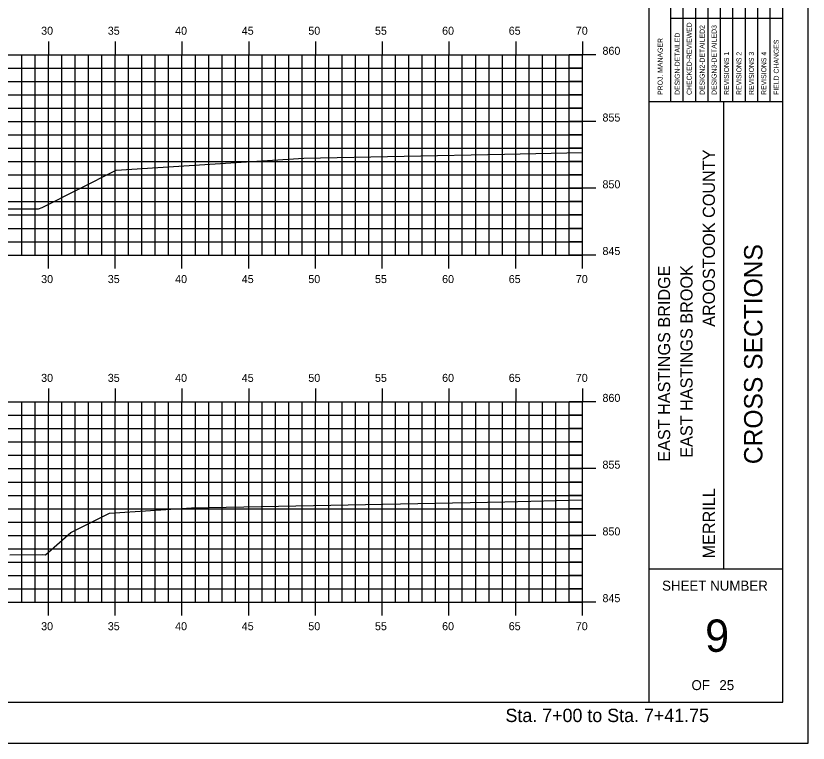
# Model space of a CAD drawing. Extents: x 2194004 to 2194525, y 863888 to 863998.
# Drawn here: x 2194282.5 to 2194341.9, y 863888.4 to 863942.9 of the extents above; entities that cross this region are included whole.
import ezdxf

# ---------------------------------------------------------------- set-up
doc = ezdxf.new("R2010")
doc.units = 0
for name, color, linetype in [('BORDER', 7, 'Continuous'), ('BRIDGE_TITLE', 7, 'Continuous'), ('H_V ANNOTATION', 7, 'Continuous'), ('MAJOR', 7, 'Continuous'), ('MINOR', 7, 'Continuous'), ('PLOT BOUNDARY', 7, 'Continuous'), ('S_Roadway_Centerline', 7, 'Continuous')]:
    doc.layers.add(name, color=color, linetype=linetype)

msp = doc.modelspace()

# ---------------------------------------------------------------- linework, layer by layer
at = {"layer": 'BORDER'}
for p, q in [((2194329.986, 863891.446), (2194329.986, 863996.446)), ((2194329.986, 863936.449), (2194339.986, 863936.449)), ((2194335.577, 863901.449), (2194335.577, 863936.449)), ((2194329.986, 863901.449), (2194339.986, 863901.449))]:
    msp.add_line(p, q, dxfattribs=at)
msp.add_lwpolyline([(2194179.986, 863891.446), (2194339.986, 863891.446), (2194339.986, 863996.446), (2194179.986, 863996.446)], close=True, dxfattribs=at)
for points in [[(2194332.534, 863936.452), (2194332.534, 863953.949)], [(2194333.466, 863953.949), (2194333.466, 863936.452)], [(2194334.397, 863936.452), (2194334.397, 863953.949)], [(2194335.329, 863936.452), (2194335.329, 863953.949)], [(2194336.261, 863936.452), (2194336.261, 863953.949)], [(2194337.192, 863936.452), (2194337.192, 863953.949)], [(2194338.124, 863936.452), (2194338.124, 863953.949)], [(2194339.056, 863936.452), (2194339.056, 863953.949)], [(2194331.602, 863936.452), (2194331.602, 863953.243)], [(2194331.601, 863942.699), (2194339.986, 863942.699)]]:
    msp.add_lwpolyline(points, dxfattribs=at)
at = {"layer": 'MAJOR'}
for p, q in [((2194284.986, 863940.948), (2194284.986, 863939.946)), ((2194289.986, 863940.948), (2194289.986, 863939.946)), ((2194294.986, 863940.948), (2194294.986, 863939.946)), ((2194299.986, 863940.948), (2194299.986, 863939.946)), ((2194304.986, 863940.948), (2194304.986, 863939.946)), ((2194309.986, 863940.948), (2194309.986, 863939.946)), ((2194314.986, 863940.948), (2194314.986, 863939.946)), ((2194319.986, 863940.948), (2194319.986, 863939.946)), ((2194324.986, 863940.948), (2194324.986, 863939.946)), ((2194184.986, 863939.946), (2194324.986, 863939.946)), ((2194184.986, 863939.946), (2194324.986, 863939.946)), ((2194284.986, 863924.946), (2194284.986, 863939.946)), ((2194289.986, 863924.946), (2194289.986, 863939.946)), ((2194294.986, 863924.946), (2194294.986, 863939.946)), ((2194299.986, 863924.946), (2194299.986, 863939.946)), ((2194304.986, 863924.946), (2194304.986, 863939.946)), ((2194309.986, 863924.946), (2194309.986, 863939.946)), ((2194314.986, 863924.946), (2194314.986, 863939.946)), ((2194319.986, 863924.946), (2194319.986, 863939.946)), ((2194325.988, 863939.946), (2194323.984, 863939.946)), ((2194324.986, 863924.946), (2194324.986, 863939.946)), ((2194324.986, 863924.946), (2194324.986, 863939.946)), ((2194184.986, 863934.946), (2194324.986, 863934.946)), ((2194325.988, 863934.946), (2194323.984, 863934.946)), ((2194184.986, 863929.946), (2194324.986, 863929.946)), ((2194325.988, 863929.946), (2194323.984, 863929.946)), ((2194184.986, 863924.946), (2194324.986, 863924.946)), ((2194284.986, 863923.944), (2194284.986, 863924.946)), ((2194289.986, 863923.944), (2194289.986, 863924.946)), ((2194294.986, 863923.944), (2194294.986, 863924.946)), ((2194299.986, 863923.944), (2194299.986, 863924.946)), ((2194304.986, 863923.944), (2194304.986, 863924.946)), ((2194309.986, 863923.944), (2194309.986, 863924.946)), ((2194314.986, 863923.944), (2194314.986, 863924.946)), ((2194319.986, 863923.944), (2194319.986, 863924.946)), ((2194325.988, 863924.946), (2194323.984, 863924.946)), ((2194324.986, 863923.944), (2194324.986, 863924.946)), ((2194284.986, 863914.948), (2194284.986, 863913.946)), ((2194289.986, 863914.948), (2194289.986, 863913.946)), ((2194294.986, 863914.948), (2194294.986, 863913.946)), ((2194299.986, 863914.948), (2194299.986, 863913.946)), ((2194304.986, 863914.948), (2194304.986, 863913.946)), ((2194309.986, 863914.948), (2194309.986, 863913.946)), ((2194314.986, 863914.948), (2194314.986, 863913.946)), ((2194319.986, 863914.948), (2194319.986, 863913.946)), ((2194324.986, 863914.948), (2194324.986, 863913.946)), ((2194184.986, 863913.946), (2194324.986, 863913.946)), ((2194184.986, 863913.946), (2194324.986, 863913.946)), ((2194284.986, 863898.946), (2194284.986, 863913.946)), ((2194289.986, 863898.946), (2194289.986, 863913.946)), ((2194294.986, 863898.946), (2194294.986, 863913.946)), ((2194299.986, 863898.946), (2194299.986, 863913.946)), ((2194304.986, 863898.946), (2194304.986, 863913.946)), ((2194309.986, 863898.946), (2194309.986, 863913.946)), ((2194314.986, 863898.946), (2194314.986, 863913.946)), ((2194319.986, 863898.946), (2194319.986, 863913.946)), ((2194325.988, 863913.946), (2194323.984, 863913.946)), ((2194324.986, 863898.946), (2194324.986, 863913.946)), ((2194324.986, 863898.946), (2194324.986, 863913.946)), ((2194184.986, 863908.946), (2194324.986, 863908.946)), ((2194325.988, 863908.946), (2194323.984, 863908.946)), ((2194184.986, 863903.946), (2194324.986, 863903.946)), ((2194325.988, 863903.946), (2194323.984, 863903.946)), ((2194184.986, 863898.946), (2194324.986, 863898.946)), ((2194284.986, 863897.944), (2194284.986, 863898.946)), ((2194289.986, 863897.944), (2194289.986, 863898.946)), ((2194294.986, 863897.944), (2194294.986, 863898.946)), ((2194299.986, 863897.944), (2194299.986, 863898.946)), ((2194304.986, 863897.944), (2194304.986, 863898.946)), ((2194309.986, 863897.944), (2194309.986, 863898.946)), ((2194314.986, 863897.944), (2194314.986, 863898.946)), ((2194319.986, 863897.944), (2194319.986, 863898.946)), ((2194325.988, 863898.946), (2194323.984, 863898.946)), ((2194324.986, 863897.944), (2194324.986, 863898.946))]:
    msp.add_line(p, q, dxfattribs=at)
at = {"layer": 'MINOR'}
for p, q in [((2194282.986, 863924.946), (2194282.986, 863939.946)), ((2194283.986, 863924.946), (2194283.986, 863939.946)), ((2194285.986, 863924.946), (2194285.986, 863939.946)), ((2194286.986, 863924.946), (2194286.986, 863939.946)), ((2194287.986, 863924.946), (2194287.986, 863939.946)), ((2194288.986, 863924.946), (2194288.986, 863939.946)), ((2194290.986, 863924.946), (2194290.986, 863939.946)), ((2194291.986, 863924.946), (2194291.986, 863939.946)), ((2194292.986, 863924.946), (2194292.986, 863939.946)), ((2194293.986, 863924.946), (2194293.986, 863939.946)), ((2194295.986, 863924.946), (2194295.986, 863939.946)), ((2194296.986, 863924.946), (2194296.986, 863939.946)), ((2194297.986, 863924.946), (2194297.986, 863939.946)), ((2194298.986, 863924.946), (2194298.986, 863939.946)), ((2194300.986, 863924.946), (2194300.986, 863939.946)), ((2194301.986, 863924.946), (2194301.986, 863939.946)), ((2194302.986, 863924.946), (2194302.986, 863939.946)), ((2194303.986, 863924.946), (2194303.986, 863939.946)), ((2194305.986, 863924.946), (2194305.986, 863939.946)), ((2194306.986, 863924.946), (2194306.986, 863939.946)), ((2194307.986, 863924.946), (2194307.986, 863939.946)), ((2194308.986, 863924.946), (2194308.986, 863939.946)), ((2194310.986, 863924.946), (2194310.986, 863939.946)), ((2194311.986, 863924.946), (2194311.986, 863939.946)), ((2194312.986, 863924.946), (2194312.986, 863939.946)), ((2194313.986, 863924.946), (2194313.986, 863939.946)), ((2194315.986, 863924.946), (2194315.986, 863939.946)), ((2194316.986, 863924.946), (2194316.986, 863939.946)), ((2194317.986, 863924.946), (2194317.986, 863939.946)), ((2194318.986, 863924.946), (2194318.986, 863939.946)), ((2194320.986, 863924.946), (2194320.986, 863939.946)), ((2194321.986, 863924.946), (2194321.986, 863939.946)), ((2194322.986, 863924.946), (2194322.986, 863939.946)), ((2194323.986, 863924.946), (2194323.986, 863939.946)), ((2194184.986, 863938.946), (2194324.986, 863938.946)), ((2194324.986, 863938.946), (2194323.984, 863938.946)), ((2194184.986, 863937.946), (2194324.986, 863937.946)), ((2194324.986, 863937.946), (2194323.984, 863937.946)), ((2194184.986, 863936.946), (2194324.986, 863936.946)), ((2194324.986, 863936.946), (2194323.984, 863936.946)), ((2194184.986, 863935.946), (2194324.986, 863935.946)), ((2194324.986, 863935.946), (2194323.984, 863935.946)), ((2194184.986, 863933.946), (2194324.986, 863933.946)), ((2194324.986, 863933.946), (2194323.984, 863933.946)), ((2194184.986, 863932.946), (2194324.986, 863932.946)), ((2194324.986, 863932.946), (2194323.984, 863932.946)), ((2194184.986, 863931.946), (2194324.986, 863931.946)), ((2194324.986, 863931.946), (2194323.984, 863931.946)), ((2194184.986, 863930.946), (2194324.986, 863930.946)), ((2194324.986, 863930.946), (2194323.984, 863930.946)), ((2194184.986, 863928.946), (2194324.986, 863928.946)), ((2194324.986, 863928.946), (2194323.984, 863928.946)), ((2194184.986, 863927.946), (2194324.986, 863927.946)), ((2194324.986, 863927.946), (2194323.984, 863927.946)), ((2194184.986, 863926.946), (2194324.986, 863926.946)), ((2194324.986, 863926.946), (2194323.984, 863926.946)), ((2194184.986, 863925.946), (2194324.986, 863925.946)), ((2194324.986, 863925.946), (2194323.984, 863925.946)), ((2194282.986, 863898.946), (2194282.986, 863913.946)), ((2194283.986, 863898.946), (2194283.986, 863913.946)), ((2194285.986, 863898.946), (2194285.986, 863913.946)), ((2194286.986, 863898.946), (2194286.986, 863913.946)), ((2194287.986, 863898.946), (2194287.986, 863913.946)), ((2194288.986, 863898.946), (2194288.986, 863913.946)), ((2194290.986, 863898.946), (2194290.986, 863913.946)), ((2194291.986, 863898.946), (2194291.986, 863913.946)), ((2194292.986, 863898.946), (2194292.986, 863913.946)), ((2194293.986, 863898.946), (2194293.986, 863913.946)), ((2194295.986, 863898.946), (2194295.986, 863913.946)), ((2194296.986, 863898.946), (2194296.986, 863913.946)), ((2194297.986, 863898.946), (2194297.986, 863913.946)), ((2194298.986, 863898.946), (2194298.986, 863913.946)), ((2194300.986, 863898.946), (2194300.986, 863913.946)), ((2194301.986, 863898.946), (2194301.986, 863913.946)), ((2194302.986, 863898.946), (2194302.986, 863913.946)), ((2194303.986, 863898.946), (2194303.986, 863913.946)), ((2194305.986, 863898.946), (2194305.986, 863913.946)), ((2194306.986, 863898.946), (2194306.986, 863913.946)), ((2194307.986, 863898.946), (2194307.986, 863913.946)), ((2194308.986, 863898.946), (2194308.986, 863913.946)), ((2194310.986, 863898.946), (2194310.986, 863913.946)), ((2194311.986, 863898.946), (2194311.986, 863913.946)), ((2194312.986, 863898.946), (2194312.986, 863913.946)), ((2194313.986, 863898.946), (2194313.986, 863913.946)), ((2194315.986, 863898.946), (2194315.986, 863913.946)), ((2194316.986, 863898.946), (2194316.986, 863913.946)), ((2194317.986, 863898.946), (2194317.986, 863913.946)), ((2194318.986, 863898.946), (2194318.986, 863913.946)), ((2194320.986, 863898.946), (2194320.986, 863913.946)), ((2194321.986, 863898.946), (2194321.986, 863913.946)), ((2194322.986, 863898.946), (2194322.986, 863913.946)), ((2194323.986, 863898.946), (2194323.986, 863913.946)), ((2194184.986, 863912.946), (2194324.986, 863912.946)), ((2194324.986, 863912.946), (2194323.984, 863912.946)), ((2194184.986, 863911.946), (2194324.986, 863911.946)), ((2194324.986, 863911.946), (2194323.984, 863911.946)), ((2194184.986, 863910.946), (2194324.986, 863910.946)), ((2194324.986, 863910.946), (2194323.984, 863910.946)), ((2194184.986, 863909.946), (2194324.986, 863909.946)), ((2194324.986, 863909.946), (2194323.984, 863909.946)), ((2194184.986, 863907.946), (2194324.986, 863907.946)), ((2194324.986, 863907.946), (2194323.984, 863907.946)), ((2194184.986, 863906.946), (2194324.986, 863906.946)), ((2194324.986, 863906.946), (2194323.984, 863906.946)), ((2194184.986, 863905.946), (2194324.986, 863905.946)), ((2194324.986, 863905.946), (2194323.984, 863905.946)), ((2194184.986, 863904.946), (2194324.986, 863904.946)), ((2194324.986, 863904.946), (2194323.984, 863904.946)), ((2194184.986, 863902.946), (2194324.986, 863902.946)), ((2194324.986, 863902.946), (2194323.984, 863902.946)), ((2194184.986, 863901.946), (2194324.986, 863901.946)), ((2194324.986, 863901.946), (2194323.984, 863901.946)), ((2194184.986, 863900.946), (2194324.986, 863900.946)), ((2194324.986, 863900.946), (2194323.984, 863900.946)), ((2194184.986, 863899.946), (2194324.986, 863899.946)), ((2194324.986, 863899.946), (2194323.984, 863899.946))]:
    msp.add_line(p, q, dxfattribs=at)
at = {"layer": 'PLOT BOUNDARY'}
msp.add_lwpolyline([(2194171.893, 863888.387), (2194341.893, 863888.387), (2194341.893, 863998.387), (2194171.893, 863998.387)], close=True, dxfattribs=at)
at = {"layer": 'S_Roadway_Centerline'}
for points in [[(2194281.523, 863928.402), (2194284.108, 863928.415), (2194284.225, 863928.403), (2194284.505, 863928.498), (2194290.063, 863931.291), (2194304.109, 863932.211), (2194319.136, 863932.499), (2194324.986, 863932.636)], [(2194282.094, 863902.5), (2194284.53, 863902.509), (2194284.77, 863902.497), (2194286.649, 863904.16), (2194289.544, 863905.615), (2194295.708, 863906.019), (2194319.166, 863906.469), (2194324.986, 863906.605)]]:
    msp.add_lwpolyline(points, dxfattribs=at)

# ---------------------------------------------------------------- texts
at = {"layer": 'BORDER'}
for s, height, rotation, p in [('CHECKED-REVIEWED', 0.37275, 90, (2194333.167, 863936.937)), ('DESIGN2-DETAILED2', 0.37275, 90, (2194334.136, 863936.937)), ('DESIGN3-DETAILED3', 0.37275, 90, (2194335.031, 863936.937)), ('PROJ. MANAGER', 0.37275, 90, (2194330.991, 863936.937)), ('DESIGN-DETAILED', 0.37275, 90, (2194332.273, 863936.937)), ('FIELD CHANGES', 0.37275, 90, (2194339.689, 863936.937)), ('REVISIONS 1', 0.37275, 90, (2194335.962, 863936.937)), ('REVISIONS 2', 0.37275, 90, (2194336.894, 863936.937)), ('REVISIONS 3', 0.37275, 90, (2194337.826, 863936.937)), ('REVISIONS 4', 0.37275, 90, (2194338.758, 863936.937)), ('CROSS SECTIONS', 1.37787, 90, (2194338.471, 863909.283)), ('SHEET NUMBER', 0.74527, 360, (2194330.952, 863899.812)), ('9', 2.419, 360, (2194334.173, 863895.228)), ('OF', 0.7453, 360, (2194333.153, 863892.359)), ('25', 0.7453, 360, (2194335.243, 863892.359))]:
    msp.add_text(s, height=height, rotation=rotation, dxfattribs=at).set_placement(p)
at = {"layer": 'BRIDGE_TITLE'}
for s, height, p in [('AROOSTOOK COUNTY', 0.90716, (2194334.907, 863919.571)), ('EAST HASTINGS BRIDGE', 0.90716, (2194331.553, 863909.466)), ('EAST HASTINGS BROOK', 0.90716, (2194333.23, 863909.763)), ('MERRILL', 0.9072, (2194334.907, 863902.222))]:
    msp.add_text(s, height=height, rotation=90, dxfattribs=at).set_placement(p)
at = {"layer": 'H_V ANNOTATION'}
for s, height, p in [('30', 0.6, (2194284.435, 863941.446)), ('35', 0.6, (2194289.427, 863941.446)), ('40', 0.6, (2194294.472, 863941.446)), ('45', 0.6, (2194299.464, 863941.446)), ('50', 0.6, (2194304.451, 863941.446)), ('55', 0.6, (2194309.443, 863941.446)), ('60', 0.6, (2194314.472, 863941.446)), ('65', 0.6, (2194319.464, 863941.446)), ('70', 0.6, (2194324.488, 863941.446)), ('860', 0.6, (2194326.486, 863939.946)), ('855', 0.6, (2194326.486, 863934.946)), ('850', 0.6, (2194326.486, 863929.946)), ('845', 0.6, (2194326.486, 863924.946)), ('30', 0.6, (2194284.435, 863922.846)), ('35', 0.6, (2194289.427, 863922.846)), ('40', 0.6, (2194294.472, 863922.846)), ('45', 0.6, (2194299.464, 863922.846)), ('50', 0.6, (2194304.451, 863922.846)), ('55', 0.6, (2194309.443, 863922.846)), ('60', 0.6, (2194314.472, 863922.846)), ('65', 0.6, (2194319.464, 863922.846)), ('70', 0.6, (2194324.488, 863922.846)), ('30', 0.6, (2194284.435, 863915.446)), ('35', 0.6, (2194289.427, 863915.446)), ('40', 0.6, (2194294.472, 863915.446)), ('45', 0.6, (2194299.464, 863915.446)), ('50', 0.6, (2194304.451, 863915.446)), ('55', 0.6, (2194309.443, 863915.446)), ('60', 0.6, (2194314.472, 863915.446)), ('65', 0.6, (2194319.464, 863915.446)), ('70', 0.6, (2194324.488, 863915.446)), ('860', 0.6, (2194326.486, 863913.946)), ('855', 0.6, (2194326.486, 863908.946)), ('850', 0.6, (2194326.486, 863903.946)), ('845', 0.6, (2194326.486, 863898.946)), ('30', 0.6, (2194284.435, 863896.846)), ('35', 0.6, (2194289.427, 863896.846)), ('40', 0.6, (2194294.472, 863896.846)), ('45', 0.6, (2194299.464, 863896.846)), ('50', 0.6, (2194304.451, 863896.846)), ('55', 0.6, (2194309.443, 863896.846)), ('60', 0.6, (2194314.472, 863896.846)), ('65', 0.6, (2194319.464, 863896.846)), ('70', 0.6, (2194324.488, 863896.846)), ('Sta. 7+00 to Sta. 7+41.75', 1.0002, (2194319.219, 863889.966))]:
    msp.add_text(s, height=height, dxfattribs=at).set_placement(p)

doc.saveas('drawing.dxf')
